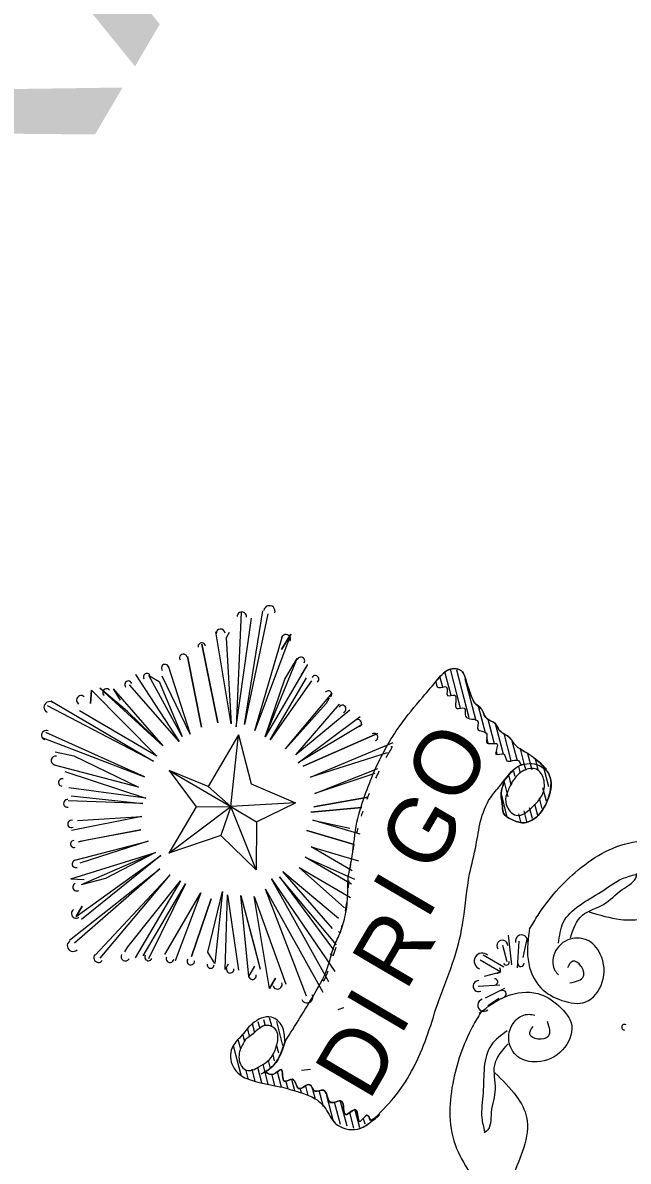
# Model space of a CAD drawing. Extents: x 423683 to 425040, y 89137 to 90655.
# Drawn here: x 424098.3 to 424128.2, y 90009.2 to 90065.6 of the extents above; entities that cross this region are included whole.
import ezdxf

# ---------------------------------------------------------------- set-up
doc = ezdxf.new("R2010")
doc.units = 0
doc.layers.add('BORDER', color=7, linetype='Continuous')

msp = doc.modelspace()

# ---------------------------------------------------------------- linework, layer by layer
at = {"layer": 'BORDER'}
for p, q in [((424109.104, 90036.405), (424108.854, 90030.73)), ((424109.258, 90030.836), (424110.167, 90036.465)), ((424110.422, 90036.316), (424109.258, 90030.836)), ((424108.854, 90030.73), (424109.614, 90036.106)), ((424108.506, 90035.386), (424108.357, 90035.132)), ((424109.768, 90030.536), (424111.141, 90035.208)), ((424107.941, 90030.924), (424107.144, 90034.816)), ((424107.144, 90034.816), (424107.941, 90030.924)), ((424106.441, 90034.202), (424107.133, 90030.714)), ((424110.277, 90030.237), (424111.861, 90034.101)), ((424112.37, 90033.802), (424110.277, 90030.237)), ((424112.37, 90033.802), (424112.071, 90033.293)), ((424119.474, 90032.283), (424119.191, 90033.375)), ((424119.946, 90031.644), (424119.443, 90033.577)), ((424120.373, 90031.173), (424119.76, 90033.533)), ((424106.025, 90029.995), (424103.568, 90032.808)), ((424106.175, 90030.249), (424104.526, 90033.272)), ((424110.531, 90030.088), (424112.326, 90033.143)), ((424119.065, 90032.684), (424118.938, 90033.173)), ((424120.716, 90031.028), (424120.179, 90033.095)), ((424105.217, 90029.785), (424102.101, 90032.642)), ((424102.76, 90032.597), (424103.119, 90032.044)), ((424102.76, 90032.597), (424105.217, 90029.785)), ((424111.295, 90029.639), (424113.599, 90032.396)), ((424104.768, 90029.021), (424099.526, 90031.757)), ((424099.676, 90032.011), (424104.768, 90029.021)), ((424121.176, 90030.432), (424120.838, 90031.733)), ((424104.918, 90029.275), (424101.099, 90031.518)), ((424121.625, 90029.881), (424121.31, 90031.093)), ((424115.082, 90030.84), (424111.91, 90028.936)), ((424120.833, 90030.58), (424120.799, 90030.71)), ((424122.063, 90029.369), (424121.673, 90030.867)), ((424099.288, 90030.184), (424104.32, 90028.257)), ((424104.32, 90028.257), (424099.438, 90030.439)), ((424108.959, 90030.326), (424107.464, 90027.78)), ((424112.164, 90028.787), (424115.846, 90030.391)), ((424115.846, 90030.391), (424112.164, 90028.787)), ((424121.31, 90029.917), (424121.239, 90030.191)), ((424122.452, 90029.047), (424122.102, 90030.393)), ((424122.758, 90029.041), (424122.506, 90030.013)), ((424099.902, 90029.481), (424100.816, 90029.287)), ((424121.758, 90029.369), (424121.716, 90029.531)), ((424123.099, 90028.904), (424122.909, 90029.637)), ((424123.483, 90028.602), (424123.277, 90029.392)), ((424123.1, 90028.902), (424123.099, 90028.904)), ((424123.185, 90028.572), (424123.1, 90028.902)), ((424123.801, 90028.553), (424123.651, 90029.128)), ((424100.367, 90028.523), (424104.38, 90027.194)), ((424122.44, 90027.92), (424122.343, 90028.291)), ((424122.653, 90028.273), (424122.588, 90028.523)), ((424122.918, 90028.427), (424122.832, 90028.756)), ((424124.312, 90027.76), (424124.05, 90028.766)), ((424104.38, 90027.194), (424100.577, 90027.715)), ((424122.044, 90027.81), (424122.104, 90028.062)), ((424122.104, 90028.062), (424122.049, 90027.831)), ((424122.307, 90027.259), (424122.101, 90028.05)), ((424124.193, 90027.044), (424124.02, 90027.709)), ((424100.682, 90027.311), (424104.231, 90026.939)), ((424122.243, 90026.328), (424121.964, 90027.404)), ((424123.982, 90026.684), (424123.849, 90027.192)), ((424106.866, 90026.762), (424108.588, 90026.778)), ((424109.861, 90026.03), (424111.776, 90026.96)), ((424112.54, 90026.511), (424115.07, 90026.738)), ((424115.07, 90026.738), (424112.54, 90026.511)), ((424123.499, 90026.193), (424123.363, 90026.718)), ((424123.767, 90026.337), (424123.622, 90026.895)), ((424122.934, 90026.018), (424122.829, 90026.424)), ((424123.232, 90026.048), (424123.096, 90026.571)), ((424104.142, 90025.622), (424101.058, 90025.036)), ((424104.502, 90025.068), (424101.119, 90023.973)), ((424109.832, 90023.65), (424108.095, 90025.355)), ((424100.671, 90023.209), (424104.861, 90024.515)), ((424104.861, 90024.515), (424101.18, 90022.91)), ((424105.116, 90024.365), (424101.196, 90021.188)), ((424112.556, 90024.79), (424114.892, 90024.103)), ((424114.593, 90023.593), (424112.556, 90024.79)), ((424100.598, 90020.17), (424105.072, 90023.706)), ((424100.671, 90023.209), (424101.329, 90023.165)), ((424105.072, 90023.706), (424100.853, 90020.02)), ((424105.581, 90023.407), (424101.871, 90019.422)), ((424102.126, 90019.273), (424105.581, 90023.407)), ((424104.251, 90019.394), (424106.345, 90022.959)), ((424106.345, 90022.959), (424104.506, 90019.244)), ((424110.297, 90022.692), (424113.131, 90017.604)), ((424112.322, 90017.394), (424110.297, 90022.692)), ((424105.314, 90019.455), (424107.109, 90022.51)), ((424108.171, 90022.571), (424107.8, 90019.022)), ((424108.426, 90022.421), (424108.968, 90018.679)), ((424109.085, 90022.377), (424110.031, 90018.739)), ((424109.477, 90018.38), (424109.085, 90022.377)), ((424109.744, 90022.332), (424111.304, 90017.992)), ((424122.486, 90018.958), (424122.321, 90020.425)), ((424103.338, 90019.588), (424103.488, 90019.843)), ((424122.022, 90019.916), (424122.232, 90019.108)), ((424122.83, 90020.126), (424122.741, 90018.809)), ((424123.04, 90019.318), (424123.234, 90020.231)), ((424121.064, 90019.451), (424122.082, 90018.853)), ((424109.477, 90018.38), (424109.776, 90018.889)), ((424120.914, 90019.197), (424121.933, 90018.599)), ((424121.125, 90018.388), (424121.933, 90018.599)), ((424121.888, 90017.94), (424120.825, 90017.879)), ((424121.185, 90017.325), (424122.143, 90017.79)), ((424121.844, 90017.281), (424121.29, 90016.921)), ((424113.89, 90016.737), (424114.17, 90016.832)), ((424114.173, 90016.832), (424114.173, 90016.832)), ((424109.78, 90015.581), (424109.662, 90016.035)), ((424110.033, 90015.78), (424109.941, 90016.134)), ((424110.301, 90015.922), (424110.221, 90016.232)), ((424110.605, 90015.926), (424110.5, 90016.33)), ((424111.161, 90014.964), (424110.854, 90016.143)), ((424109.282, 90015.148), (424109.184, 90015.526)), ((424109.516, 90015.424), (424109.421, 90015.788)), ((424109.104, 90013.488), (424108.724, 90014.949)), ((424109.074, 90014.774), (424108.952, 90015.246)), ((424110.956, 90014.578), (424110.848, 90014.994)), ((424110.541, 90013.826), (424110.44, 90014.216)), ((424110.751, 90014.193), (424110.671, 90014.502)), ((424109.449, 90013.332), (424109.347, 90013.724)), ((424109.792, 90013.186), (424109.636, 90013.789)), ((424110.116, 90013.116), (424109.918, 90013.875)), ((424110.439, 90013.046), (424110.187, 90014.017)), ((424111.087, 90012.9), (424110.889, 90013.662)), ((424112.075, 90013.746), (424112.528, 90013.782)), ((424110.762, 90012.976), (424110.609, 90013.563)), ((424111.417, 90012.806), (424111.312, 90013.209)), ((424111.746, 90012.712), (424111.597, 90013.284)), ((424112.078, 90012.61), (424112.014, 90012.856)), ((424112.417, 90012.478), (424112.294, 90012.951)), ((424112.771, 90012.289), (424112.626, 90012.847)), ((424113.172, 90011.92), (424112.961, 90012.734)), ((424113.647, 90011.268), (424113.336, 90012.466)), ((424114.01, 90011.047), (424113.719, 90012.163)), ((424114.337, 90010.962), (424114.016, 90012.195)), ((424114.664, 90010.877), (424114.466, 90011.639)), ((424114.965, 90010.893), (424114.738, 90011.767)), ((424115.742, 90011.425), (424115.739, 90011.438)), ((424115.224, 90011.07), (424115.152, 90011.346)), ((424115.483, 90011.248), (424115.465, 90011.317))]:
    msp.add_line(p, q, dxfattribs=at)
for points in [[(424108.357, 90035.132), (424108.6, 90030.88), (424107.848, 90035.431)], [(424111.546, 90035.314), (424111.097, 90034.55), (424111.546, 90035.314), (424109.768, 90030.536)], [(424107.133, 90030.714), (424106.441, 90034.202), (424106.441, 90034.202)], [(424110.277, 90030.237), (424111.263, 90033.083), (424111.861, 90034.101)], [(424105.483, 90033.737), (424105.483, 90033.737), (424106.579, 90030.354)], [(424103.867, 90033.317), (424103.867, 90033.317), (424106.025, 90029.995)], [(424104.526, 90033.272), (424105.035, 90032.973), (424106.175, 90030.249)], [(424106.579, 90030.354), (424105.184, 90033.228), (424105.184, 90033.228)], [(424112.58, 90032.994), (424112.58, 90032.994), (424110.531, 90030.088)], [(424101.697, 90032.537), (424101.652, 90031.878), (424101.697, 90032.537), (424104.918, 90029.275)], [(424105.217, 90029.785), (424103.479, 90031.49), (424102.101, 90032.642)], [(424113.449, 90032.141), (424113.3, 90031.886), (424111.295, 90029.639)], [(424111.804, 90029.34), (424113.958, 90031.842), (424113.958, 90031.842)], [(424114.468, 90031.543), (424114.468, 90031.543), (424111.804, 90029.34)], [(424111.91, 90028.936), (424114.977, 90031.244), (424114.977, 90031.244)], [(424111.776, 90026.96), (424108.588, 90026.778), (424108.959, 90030.326), (424109.59, 90027.901), (424111.776, 90026.96)], [(424116.311, 90029.433), (424112.524, 90028.233), (424116.61, 90029.943)], [(424100.816, 90029.287), (424104.021, 90027.748), (424099.858, 90028.822)], [(424105.532, 90028.572), (424106.866, 90026.762), (424105.52, 90024.47)], [(424108.588, 90026.778), (424107.464, 90027.78), (424105.532, 90028.572), (424108.588, 90026.778)], [(424115.713, 90028.415), (424112.734, 90027.425), (424115.862, 90028.67)], [(424115.369, 90027.247), (424112.69, 90026.766), (424115.369, 90027.247)], [(424104.231, 90026.939), (424100.533, 90027.056), (424100.533, 90027.056)], [(424105.52, 90024.47), (424108.588, 90026.778), (424108.095, 90025.355), (424105.52, 90024.47)], [(424109.832, 90023.65), (424108.588, 90026.778), (424109.861, 90026.03), (424109.832, 90023.65)], [(424104.186, 90026.281), (424100.699, 90025.589), (424100.699, 90025.589)], [(424100.998, 90026.099), (424100.998, 90026.099), (424104.186, 90026.281)], [(424114.981, 90025.42), (424112.645, 90026.107), (424114.472, 90025.719)], [(424101.058, 90025.036), (424101.463, 90025.141), (424104.142, 90025.622)], [(424114.682, 90024.911), (424112.346, 90025.598), (424114.682, 90024.911)], [(424100.864, 90024.122), (424100.864, 90024.122), (424104.502, 90025.068)], [(424100.941, 90021.338), (424101.24, 90021.847), (424100.941, 90021.338), (424105.116, 90024.365)], [(424104.861, 90024.515), (424102.392, 90023.225), (424101.18, 90022.91)], [(424114.205, 90021.767), (424111.958, 90023.771), (424114.504, 90022.276)], [(424114.549, 90022.935), (424112.257, 90024.28), (424114.698, 90023.189)], [(424113.43, 90018.113), (424110.596, 90023.201), (424113.729, 90018.622)], [(424113.818, 90019.94), (424111, 90023.306), (424113.668, 90019.685)], [(424113.607, 90020.748), (424111.15, 90023.561), (424113.906, 90021.257)], [(424103.488, 90019.843), (424106.09, 90023.108), (424103.847, 90019.289)], [(424107.109, 90022.51), (424105.824, 90019.156), (424105.824, 90019.156)], [(424107.618, 90022.211), (424106.632, 90019.366), (424106.632, 90019.366)], [(424106.632, 90019.366), (424106.632, 90019.366), (424107.618, 90022.211)], [(424107.8, 90019.022), (424107.44, 90019.576), (424108.171, 90022.571)], [(424108.459, 90018.978), (424108.309, 90018.723), (424108.426, 90022.421)], [(424109.085, 90022.377), (424109.715, 90019.952), (424110.031, 90018.739)], [(424110.496, 90017.782), (424110.795, 90018.291), (424110.496, 90017.782), (424109.744, 90022.332)]]:
    msp.add_lwpolyline(points, dxfattribs=at)
for centre, radius, start, end in [((424110.493, 90036.436), 0.283, 344.7592, 170.3939), ((424109.126, 90036.175), 0.232, 352.9696, 179.3412), ((424108.08, 90035.347), 0.218, 4.9526, 184.4129), ((424111.304, 90035.058), 0.232, 337.7571, 163.4762), ((424107.146, 90034.695), 0.184, 5.5411, 190.9827), ((424106.241, 90034.13), 0.192, 57.9215, 208.9007), ((424106.237, 90034.132), 0.192, 12.3177, 56.6834), ((424112.049, 90033.979), 0.192, 330.4729, 156.0308), ((424112.049, 90033.979), 0.192, 330.4729, 156.0308), ((424104.428, 90033.201), 0.169, 22.7326, 215.433), ((424105.33, 90033.633), 0.182, 1.1105, 225.128), ((424103.517, 90032.811), 0.182, 20.3855, 222.304), ((424112.758, 90033.082), 0.182, 308.3855, 150.304), ((424101.188, 90032.039), 0.232, 49.7571, 235.4762), ((424102.445, 90032.414), 0.192, 42.4729, 228.0308), ((424102.445, 90032.414), 0.192, 42.4729, 228.0308), ((424113.41, 90032.336), 0.169, 310.7326, 143.433), ((424099.627, 90031.694), 0.283, 56.7592, 242.3939), ((424114.099, 90031.611), 0.182, 289.1105, 153.128), ((424114.853, 90030.898), 0.192, 345.9215, 136.9007), ((424099.452, 90030.314), 0.232, 64.9696, 251.3412), ((424114.854, 90030.902), 0.192, 300.3177, 344.6834), ((424115.67, 90030.212), 0.184, 293.5411, 118.9827), ((424129.738, 90021.796), 15.38, 148.8856, 151.2144), ((424116.579, 90029.525), 0.218, 92.2091, 112.4129), ((424099.917, 90029.062), 0.218, 76.9526, 256.4129), ((424129.738, 90021.796), 15.38, 154.0526, 155.4636), ((424100.248, 90027.973), 0.184, 77.5411, 262.9827), ((424129.738, 90021.796), 15.38, 158.552, 159.6793), ((424100.506, 90026.937), 0.192, 129.9215, 280.9007), ((424100.503, 90026.935), 0.192, 84.3177, 128.6834), ((424100.697, 90025.918), 0.182, 73.1105, 297.128), ((424129.738, 90021.796), 15.38, 162.0099, 162.9488), ((424129.738, 90021.796), 15.38, 165.3229, 166.1435), ((424100.829, 90024.926), 0.169, 94.7326, 287.433), ((424129.765, 90021.93), 15.38, 169.0543, 169.9289), ((424100.918, 90023.939), 0.182, 92.3855, 294.304), ((424129.738, 90021.796), 15.38, 171.6724, 172.6165), ((424100.965, 90022.797), 0.192, 114.4729, 300.0308), ((424100.965, 90022.797), 0.192, 114.4729, 300.0308), ((424129.738, 90021.796), 15.38, 175.1264, 176.3922), ((424100.933, 90021.486), 0.232, 121.7571, 307.4762), ((424097.203, 90024.933), 17.364, 349.0245, 350.3795), ((424114.041, 90020.72), 0.184, 221.5411, 257.5802), ((424097.203, 90024.933), 17.364, 345.3453, 346.6337), ((424122.96, 90020.126), 0.303, 350.446, 191.9754), ((424100.779, 90019.895), 0.283, 128.7592, 314.3939), ((424097.203, 90024.933), 17.364, 341.5047, 342.8987), ((424122.013, 90019.894), 0.273, 4.3993, 212.0936), ((424102.038, 90019.302), 0.232, 136.9696, 323.3412), ((424103.371, 90019.357), 0.218, 148.9526, 328.4129), ((424104.51, 90019.336), 0.184, 149.5411, 334.9827), ((424105.576, 90019.257), 0.192, 156.3177, 200.6834), ((424113.669, 90019.644), 0.218, 220.9526, 270.286), ((424121.02, 90019.133), 0.399, 149.5766, 251.1525), ((424121.02, 90019.133), 0.399, 48.0008, 149.5766), ((424105.574, 90019.261), 0.192, 201.9215, 352.9007), ((424106.603, 90019.127), 0.182, 145.1105, 9.128), ((424107.587, 90018.946), 0.169, 166.7326, 359.433), ((424108.553, 90018.726), 0.182, 164.3855, 6.304), ((424121.77, 90018.693), 0.154, 329.5766, 43.2503), ((424122.213, 90019.083), 0.144, 202.492, 10.5669), ((424122.93, 90019.021), 0.156, 182.2112, 1.5604), ((424109.654, 90018.417), 0.192, 186.4729, 12.0308), ((424109.654, 90018.417), 0.192, 186.4729, 12.0308), ((424113.309, 90018.358), 0.232, 208.9696, 239.2102), ((424097.203, 90024.933), 17.364, 337.0351, 338.7956), ((424120.839, 90017.896), 0.273, 87.0596, 294.7539), ((424121.645, 90018.115), 0.144, 288.5863, 96.6612), ((424121.77, 90018.693), 0.154, 255.9029, 329.5766), ((424110.891, 90017.982), 0.232, 193.7571, 19.4762), ((424122.048, 90017.52), 0.156, 297.5928, 116.9421), ((424112.357, 90017.344), 0.283, 200.7592, 26.3939), ((424121.098, 90016.955), 0.303, 107.1779, 308.7072), ((424128.058, 90015.863), 0.143, 58.8913, 266.9824)]:
    msp.add_arc(centre, radius, start, end, dxfattribs=at)
for points in [[(424111.289, 90015.188), (424112.703, 90017.484), (424113.438, 90019.015), (424113.658, 90019.784), (424113.962, 90020.471), (424114.226, 90021.314), (424114.362, 90022.332), (424114.381, 90023.152), (424114.551, 90024.116), (424114.786, 90025.808), (424115.212, 90027.321), (424115.679, 90028.51), (424116.952, 90030.79), (424118.074, 90032.194), (424118.826, 90033.083), (424119.45, 90033.582), (424119.993, 90033.495), (424120.226, 90032.993), (424120.415, 90032.416), (424120.708, 90031.845), (424120.948, 90031.637), (424121.245, 90031.13), (424121.662, 90030.885), (424121.845, 90030.578), (424122.332, 90030.226), (424122.696, 90029.779), (424123.099, 90029.509), (424123.576, 90029.196), (424124.2, 90028.63)], [(424124.2, 90028.63), (424123.576, 90029.196), (424123.099, 90029.509), (424122.696, 90029.779), (424122.332, 90030.226), (424121.845, 90030.578), (424121.662, 90030.885), (424121.245, 90031.13), (424120.948, 90031.637), (424120.708, 90031.845), (424120.415, 90032.416), (424120.226, 90032.993), (424119.993, 90033.495), (424119.45, 90033.582), (424118.826, 90033.083), (424118.731, 90032.972)], [(424118.729, 90032.973), (424118.849, 90032.671), (424119.259, 90032.695), (424119.306, 90032.269), (424119.653, 90032.298), (424119.76, 90031.636), (424120.131, 90031.651), (424120.193, 90031.249), (424120.801, 90030.992), (424120.798, 90030.594), (424121.22, 90030.413), (424121.262, 90029.923), (424121.757, 90029.865), (424121.696, 90029.368), (424122.092, 90029.369), (424122.236, 90029.051), (424122.823, 90029.039), (424122.951, 90028.864), (424123.108, 90028.905)], [(424118.729, 90032.973), (424118.849, 90032.671), (424119.259, 90032.695), (424119.306, 90032.269), (424119.653, 90032.298), (424119.76, 90031.636), (424120.131, 90031.651), (424120.193, 90031.249), (424120.801, 90030.992), (424120.798, 90030.594), (424121.22, 90030.413), (424121.262, 90029.923), (424121.757, 90029.865), (424121.696, 90029.368), (424122.092, 90029.369), (424122.236, 90029.051), (424122.823, 90029.039), (424122.951, 90028.864), (424123.108, 90028.905)], [(424123.359, 90020.71), (424123.781, 90021.41), (424125.765, 90023.647), (424128.659, 90025.045), (424131.613, 90025.194), (424134.357, 90027.166), (424135.304, 90027.947), (424134.563, 90028.868), (424134.125, 90028.639), (424134.355, 90028.201), (424134.35, 90027.778), (424133.946, 90027.712), (424133.431, 90027.771), (424132.914, 90028.136), (424133.093, 90029.063), (424133.691, 90029.562), (424134.122, 90029.674), (424134.844, 90029.553), (424135.623, 90029.218), (424136.371, 90028.414), (424137.035, 90027.052), (424138.589, 90024.195), (424139.186, 90023.238), (424139.654, 90022.477), (424141.135, 90021.364), (424142.492, 90020.871), (424143.566, 90020.726), (424144.734, 90020.951), (424146.123, 90021.654), (424146.63, 90022.207), (424146.661, 90022.674), (424146.409, 90023.491), (424146.088, 90023.983), (424145.808, 90024.026), (424145.596, 90023.665), (424145.762, 90023.324), (424146.026, 90023.047), (424146.003, 90022.696), (424145.674, 90022.343), (424145.492, 90022.45), (424144.948, 90022.769), (424144.79, 90023.227), (424144.919, 90023.758), (424145.007, 90024.011), (424145.113, 90024.191), (424145.4, 90024.266), (424145.896, 90024.278), (424146.41, 90024.219), (424146.916, 90024.043), (424147.188, 90023.884), (424147.419, 90023.445), (424147.46, 90022.995), (424147.444, 90022.761), (424147.152, 90022.265), (424147.039, 90021.967)], [(424111.25, 90015.177), (424111.123, 90015.917), (424110.592, 90016.362), (424109.635, 90016.026), (424109.067, 90015.395), (424108.644, 90014.844), (424108.694, 90013.917), (424109.024, 90013.524), (424109.755, 90013.194), (424111.014, 90012.921), (424112.004, 90012.639), (424112.675, 90012.377), (424113.276, 90011.825), (424113.749, 90011.115), (424114.867, 90010.824), (424115.875, 90011.53), (424116.876, 90012.672), (424118.331, 90015.543), (424118.869, 90017.19), (424119.644, 90019.296), (424120.082, 90021.168), (424120.396, 90023.445), (424120.715, 90024.888), (424120.938, 90026.054), (424121.416, 90027.204), (424121.92, 90027.839), (424122.883, 90028.804), (424123.817, 90028.821), (424124.334, 90028.351), (424124.292, 90027.212), (424123.784, 90026.346), (424123.106, 90025.979), (424122.552, 90026.104), (424122.066, 90026.457), (424122.009, 90026.922), (424121.948, 90027.324), (424122.048, 90027.831)], [(424123.111, 90028.891), (424122.883, 90028.804), (424122.104, 90028.062)], [(424122.048, 90027.831), (424121.948, 90027.324), (424122.009, 90026.922), (424122.066, 90026.457), (424122.552, 90026.104), (424123.106, 90025.979), (424123.784, 90026.346), (424124.292, 90027.212), (424124.334, 90028.351), (424124.179, 90028.61)], [(424122.478, 90027.945), (424122.21, 90026.871), (424122.698, 90026.352), (424123.575, 90026.834), (424123.997, 90027.385), (424124.051, 90028.151), (424123.701, 90028.623), (424123.071, 90028.561), (424122.594, 90028.143), (424122.406, 90027.872)], [(424126.311, 90021.565), (424127.865, 90021.199), (424128.999, 90021.262), (424130.233, 90022.116), (424131.229, 90023.293), (424132.066, 90024.199), (424132.645, 90024.77), (424133.379, 90025.189), (424134.023, 90025.662), (424134.435, 90025.845)], [(424124.796, 90020.024), (424125.028, 90021.042), (424126.894, 90022.558), (424127.95, 90023.214), (424128.624, 90023.426)], [(424125.379, 90020.289), (424125.97, 90021.4), (424127.018, 90021.939), (424127.938, 90022.674), (424128.642, 90023.354), (424128.65, 90023.471)], [(424123.364, 90020.805), (424123.283, 90019.212), (424123.92, 90017.805), (424124.963, 90017.193), (424126.135, 90017.112), (424126.953, 90018.089), (424126.857, 90019.482), (424126.173, 90020.188), (424125.254, 90020.181), (424124.542, 90019.384), (424124.613, 90018.674), (424124.787, 90018.45)], [(424125.35, 90018.059), (424126.031, 90018.388), (424125.899, 90018.891), (424125.491, 90019.13), (424125.233, 90018.796)], [(424120.869, 90016.556), (424122.22, 90017.403), (424123.76, 90017.532), (424124.803, 90016.919), (424125.444, 90015.935), (424124.989, 90014.745), (424123.725, 90014.15), (424122.776, 90014.404), (424122.335, 90015.21), (424122.684, 90016.22), (424123.339, 90016.504), (424123.618, 90016.461)], [(424111.25, 90015.177), (424111.123, 90015.917), (424110.592, 90016.362), (424109.635, 90016.026), (424109.067, 90015.395), (424108.644, 90014.844), (424108.694, 90013.917), (424109.024, 90013.524), (424109.755, 90013.194), (424111.014, 90012.921), (424112.004, 90012.639), (424112.675, 90012.377), (424113.276, 90011.825), (424113.749, 90011.115), (424114.867, 90010.824), (424115.832, 90011.486)], [(424120.95, 90016.607), (424120.543, 90015.897), (424119.557, 90013.075), (424119.746, 90009.866), (424121.055, 90007.214), (424120.669, 90003.857), (424120.448, 90002.65), (424119.283, 90002.848), (424119.269, 90003.342), (424119.764, 90003.355), (424120.131, 90003.565), (424119.992, 90003.95), (424119.69, 90004.371), (424119.119, 90004.645), (424118.396, 90004.037), (424118.251, 90003.271), (424118.364, 90002.841), (424118.821, 90002.269), (424119.494, 90001.752), (424120.56, 90001.491), (424122.073, 90001.574), (424125.325, 90001.608), (424126.452, 90001.554), (424127.344, 90001.516), (424129.038, 90000.764), (424130.129, 89999.819), (424130.779, 89998.952), (424131.152, 89997.822), (424131.214, 89996.267), (424130.979, 89995.554), (424130.585, 89995.299), (424129.749, 89995.122), (424129.163, 89995.163), (424128.99, 89995.386), (424129.202, 89995.747), (424129.58, 89995.768), (424129.951, 89995.672), (424130.246, 89995.863), (424130.394, 89996.323), (424130.212, 89996.43), (424129.668, 89996.749), (424129.192, 89996.665), (424128.79, 89996.293), (424128.612, 89996.094), (424128.506, 89995.913), (424128.582, 89995.626), (424128.812, 89995.187), (424129.114, 89994.767), (424129.514, 89994.41), (424129.786, 89994.25), (424130.282, 89994.263), (424130.694, 89994.446), (424130.891, 89994.573), (424131.183, 89995.07), (424131.387, 89995.315)], [(424109.297, 90015.226), (424109.046, 90014.742), (424109.06, 90014.035), (424109.346, 90013.734), (424109.971, 90013.899), (424110.4, 90014.18), (424110.888, 90015.124), (424110.816, 90015.731), (424110.32, 90015.956), (424109.745, 90015.595), (424109.239, 90015.212)], [(424124.234, 90016.16), (424124.279, 90015.405), (424123.776, 90015.275), (424123.368, 90015.515), (424123.534, 90015.902)], [(424122.248, 90015.686), (424121.472, 90014.987), (424121.057, 90012.619), (424120.999, 90011.377), (424121.142, 90010.686)], [(424111.29, 90015.206), (424110.568, 90013.848), (424110.061, 90013.547)], [(424110.301, 90013.655), (424110.568, 90013.848), (424111.269, 90015.167)], [(424122.301, 90015.048), (424121.619, 90013.99), (424121.659, 90012.812), (424121.465, 90011.651), (424121.214, 90010.705), (424121.115, 90010.641)], [(424110.31, 90013.633), (424110.687, 90013.545), (424111.087, 90013.776), (424111.237, 90013.189), (424111.628, 90013.292), (424111.954, 90012.834), (424112.491, 90013.018), (424112.737, 90012.707), (424113.162, 90012.757), (424113.528, 90012.143), (424114.056, 90012.199), (424114.265, 90011.543), (424114.768, 90011.781), (424114.957, 90011.204), (424115.361, 90011.499), (424115.475, 90011.299), (424115.953, 90011.55)], [(424115.832, 90011.486), (424115.475, 90011.299), (424115.361, 90011.499), (424114.957, 90011.204), (424114.768, 90011.781), (424114.265, 90011.543), (424114.056, 90012.199), (424113.528, 90012.143), (424113.162, 90012.757), (424112.737, 90012.707), (424112.491, 90013.018), (424111.954, 90012.834), (424111.628, 90013.292), (424111.237, 90013.189), (424111.087, 90013.776), (424110.687, 90013.545), (424110.31, 90013.633)], [(424121.641, 90013.613), (424122.717, 90012.434), (424123.215, 90011.412), (424123.07, 90009.918), (424122.527, 90008.475), (424122.144, 90007.303), (424121.927, 90006.519), (424121.919, 90005.674), (424121.82, 90004.882), (424121.861, 90004.432)]]:
    msp.add_spline(points, degree=3, dxfattribs=at)

# ---------------------------------------------------------------- texts
for s, height, p in [('DEPARTMENT  OF  TRANSPORTATION', 18.74937, (423967.69, 89831.543)), ('STATE  OF  MAINE ', 18.74937, (424004.433, 89968.165)), ('O', 3.247, (424119.831, 90026.681)), ('G', 3.247, (424118.546, 90023.327)), ('I', 3.247, (424118.263, 90021.096)), ('R', 3.247, (424117.233, 90017.592)), ('I', 3.247, (424116.95, 90015.361)), ('D', 3.247, (424115.41, 90012.156))]:
    msp.add_text(s, height=height, rotation=59.5766, dxfattribs=at).set_placement(p)

doc.saveas('drawing.dxf')
